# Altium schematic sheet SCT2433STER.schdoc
size 127 x 101 mm
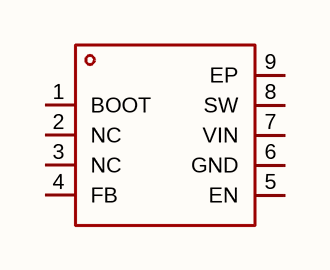
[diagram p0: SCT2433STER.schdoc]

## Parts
U?  sct2433ster  [ESOP-8_L4.9-W3.9-P1.27-LS6.0-BL-EP]  (value not drawn)

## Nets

Not connected (* = marked no-connect by the designer): U? 1(BOOT) 2(NC) 3(NC) 4(FB) 5(EN) 6(GND) 7(VIN) 8(SW) 9(EP)

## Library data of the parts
U? = sct2433ster: 功能类型:降压型;工作电压:3.8V~40V;输出电压:800mV~40V;输出电流:3.5A;输出类型:可调;; Manufacturer: SCT(芯洲科技); AddInBom: yes; ModelId: d3e00daa36c445139c055a3b9efb85d2; ModelName: ESOP-8_L4.9-W3.9-H1.6-LS6.0-P1.27; ModelTransform: 240.157,192.913,0,90,0,0,0,0,0; Function: 降压型; Output Current: 3.5A; Frequency - Switching: 570kHz; Synchronous Rectifier: 是; Number of Outputs: 1; Topology: 降压式; Quiescent Current: 25uA; Switch tube (built-in/external): 内置; Output Type: 可调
